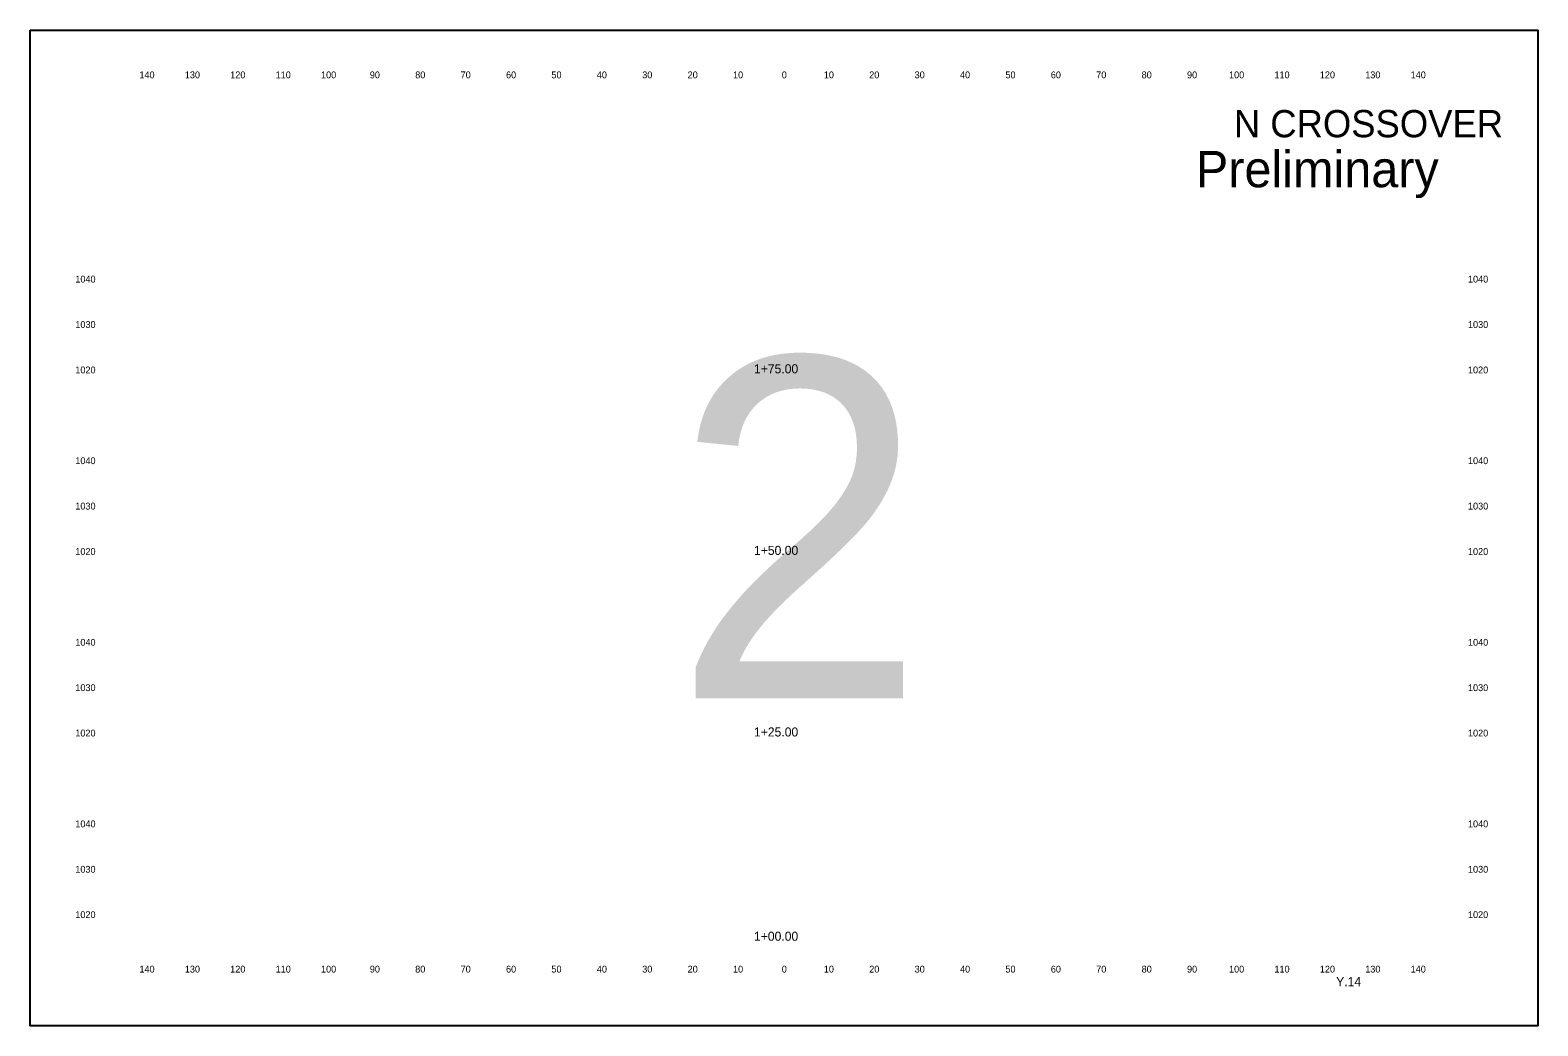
# Model space of a CAD drawing. Extents: x 10123 to 14767, y 9730 to 9950.
# Drawn here: x 10483.2 to 10815.3, y 9730.3 to 9949.6 of the extents above; entities that cross this region are included whole.
import ezdxf

# ---------------------------------------------------------------- set-up
doc = ezdxf.new("R2010")
doc.units = 0
for name, color, linetype in [('dsnTextCpn', 7, 'Continuous'), ('dsnTextCpnTitleSheetLocDesc', 7, 'Continuous'), ('dsnTextCpnTitleSheetPIN', 7, 'Continuous'), ('dsnTextCpnTitleSheetWorkType', 7, 'Continuous')]:
    doc.layers.add(name, color=color, linetype=linetype)

msp = doc.modelspace()

# ---------------------------------------------------------------- linework, layer by layer
at = {"layer": 'dsnTextCpnTitleSheetWorkType'}
msp.add_lwpolyline([(10483.21, 9949.6), (10815.29, 9949.6), (10815.29, 9730.26), (10483.21, 9730.26)], close=True, dxfattribs=at)

# ---------------------------------------------------------------- texts
at = {"layer": 'dsnTextCpn'}
for s, height, p in [('140', 1.5, (10507.27, 9939)), ('130', 1.5, (10517.27, 9939)), ('120', 1.5, (10527.27, 9939)), ('110', 1.5, (10537.27, 9939)), ('100', 1.5, (10547.27, 9939)), ('90', 1.5, (10558.02, 9939)), ('80', 1.5, (10568.02, 9939)), ('70', 1.5, (10578.02, 9939)), ('60', 1.5, (10588.02, 9939)), ('50', 1.5, (10598.02, 9939)), ('40', 1.5, (10608.02, 9939)), ('30', 1.5, (10618.02, 9939)), ('20', 1.5, (10628.02, 9939)), ('10', 1.5, (10638.02, 9939)), ('0', 1.5, (10648.76, 9939)), ('0', 1.5, (10648.76, 9939)), ('10', 1.5, (10658.02, 9939)), ('20', 1.5, (10668.02, 9939)), ('30', 1.5, (10678.02, 9939)), ('40', 1.5, (10688.02, 9939)), ('50', 1.5, (10698.02, 9939)), ('60', 1.5, (10708.02, 9939)), ('70', 1.5, (10718.02, 9939)), ('80', 1.5, (10728.02, 9939)), ('90', 1.5, (10738.02, 9939)), ('100', 1.5, (10747.27, 9939)), ('110', 1.5, (10757.27, 9939)), ('120', 1.5, (10767.27, 9939)), ('130', 1.5, (10777.27, 9939)), ('140', 1.5, (10787.27, 9939)), ('N CROSSOVER', 6, (10748.34, 9926)), ('1040', 1.5, (10493.15, 9894)), ('1040', 1.5, (10799.9, 9894)), ('1030', 1.5, (10493.15, 9884)), ('1030', 1.5, (10799.9, 9884)), ('1020', 1.5, (10493.15, 9874)), ('1+75.00', 2, (10642.64, 9874)), ('1020', 1.5, (10799.9, 9874)), ('1040', 1.5, (10493.15, 9854)), ('1040', 1.5, (10799.9, 9854)), ('1030', 1.5, (10493.15, 9844)), ('1030', 1.5, (10799.9, 9844)), ('1020', 1.5, (10493.15, 9834)), ('1+50.00', 2, (10642.64, 9834)), ('1020', 1.5, (10799.9, 9834)), ('1040', 1.5, (10493.15, 9814)), ('1040', 1.5, (10799.9, 9814)), ('1030', 1.5, (10493.15, 9804)), ('1030', 1.5, (10799.9, 9804)), ('1020', 1.5, (10493.15, 9794)), ('1+25.00', 2, (10642.64, 9794)), ('1020', 1.5, (10799.9, 9794)), ('1040', 1.5, (10493.15, 9774)), ('1040', 1.5, (10799.9, 9774)), ('1030', 1.5, (10493.15, 9764)), ('1030', 1.5, (10799.9, 9764)), ('1020', 1.5, (10493.15, 9754)), ('1020', 1.5, (10799.9, 9754)), ('1+00.00', 2, (10642.64, 9749)), ('140', 1.5, (10507.27, 9742)), ('130', 1.5, (10517.27, 9742)), ('120', 1.5, (10527.27, 9742)), ('110', 1.5, (10537.27, 9742)), ('100', 1.5, (10547.27, 9742)), ('90', 1.5, (10558.02, 9742)), ('80', 1.5, (10568.02, 9742)), ('70', 1.5, (10578.02, 9742)), ('60', 1.5, (10588.02, 9742)), ('50', 1.5, (10598.02, 9742)), ('40', 1.5, (10608.02, 9742)), ('30', 1.5, (10618.02, 9742)), ('20', 1.5, (10628.02, 9742)), ('10', 1.5, (10638.02, 9742)), ('0', 1.5, (10648.76, 9742)), ('0', 1.5, (10648.76, 9742)), ('10', 1.5, (10658.02, 9742)), ('20', 1.5, (10668.02, 9742)), ('30', 1.5, (10678.02, 9742)), ('40', 1.5, (10688.02, 9742)), ('50', 1.5, (10698.02, 9742)), ('60', 1.5, (10708.02, 9742)), ('70', 1.5, (10718.02, 9742)), ('80', 1.5, (10728.02, 9742)), ('90', 1.5, (10738.02, 9742)), ('100', 1.5, (10747.27, 9742)), ('110', 1.5, (10757.27, 9742)), ('120', 1.5, (10767.27, 9742)), ('130', 1.5, (10777.27, 9742)), ('140', 1.5, (10787.27, 9742))]:
    msp.add_text(s, height=height, dxfattribs=at).set_placement(p)
at = {"layer": 'dsnTextCpnTitleSheetLocDesc'}
msp.add_text('Preliminary', height=8, dxfattribs=at).set_placement((10739.97, 9915))
at = {"layer": 'dsnTextCpnTitleSheetPIN'}
msp.add_text('Y.14', height=2, dxfattribs=at).set_placement((10770.87, 9739))
at = {"layer": 'dsnTextCpnTitleSheetWorkType'}
msp.add_text('2', height=75, dxfattribs=at).set_placement((10624.72, 9802.43))

doc.saveas('drawing.dxf')
